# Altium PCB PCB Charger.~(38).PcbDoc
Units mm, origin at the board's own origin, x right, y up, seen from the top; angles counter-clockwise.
Board outline 70.24 x 66.94 mm, 2 copper layers (Top Layer, Bottom Layer), stack 1.57 mm thick; 117 components, 68 nets, 350 pads, 0 vias.
Unrouted connection lines stored in the file: 247.
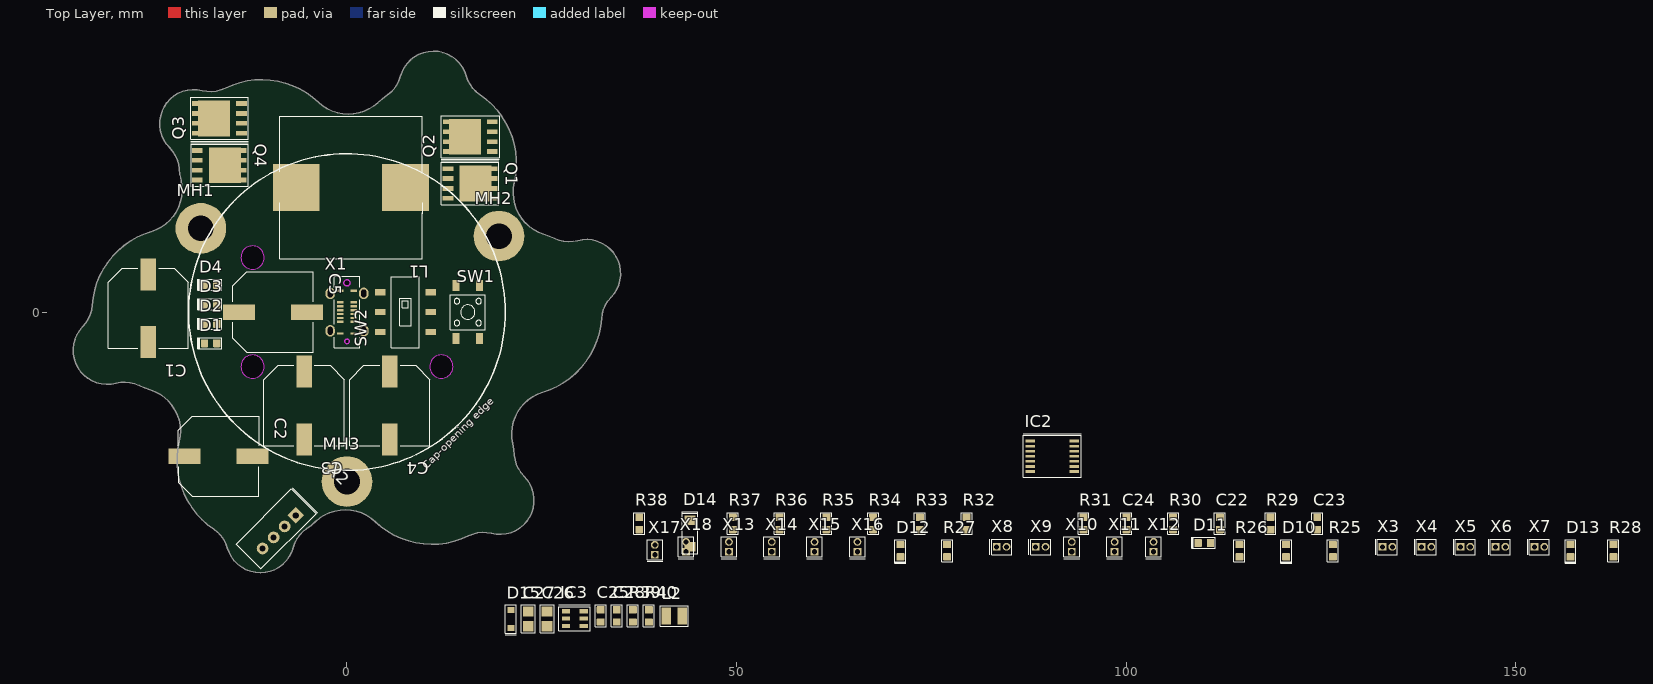
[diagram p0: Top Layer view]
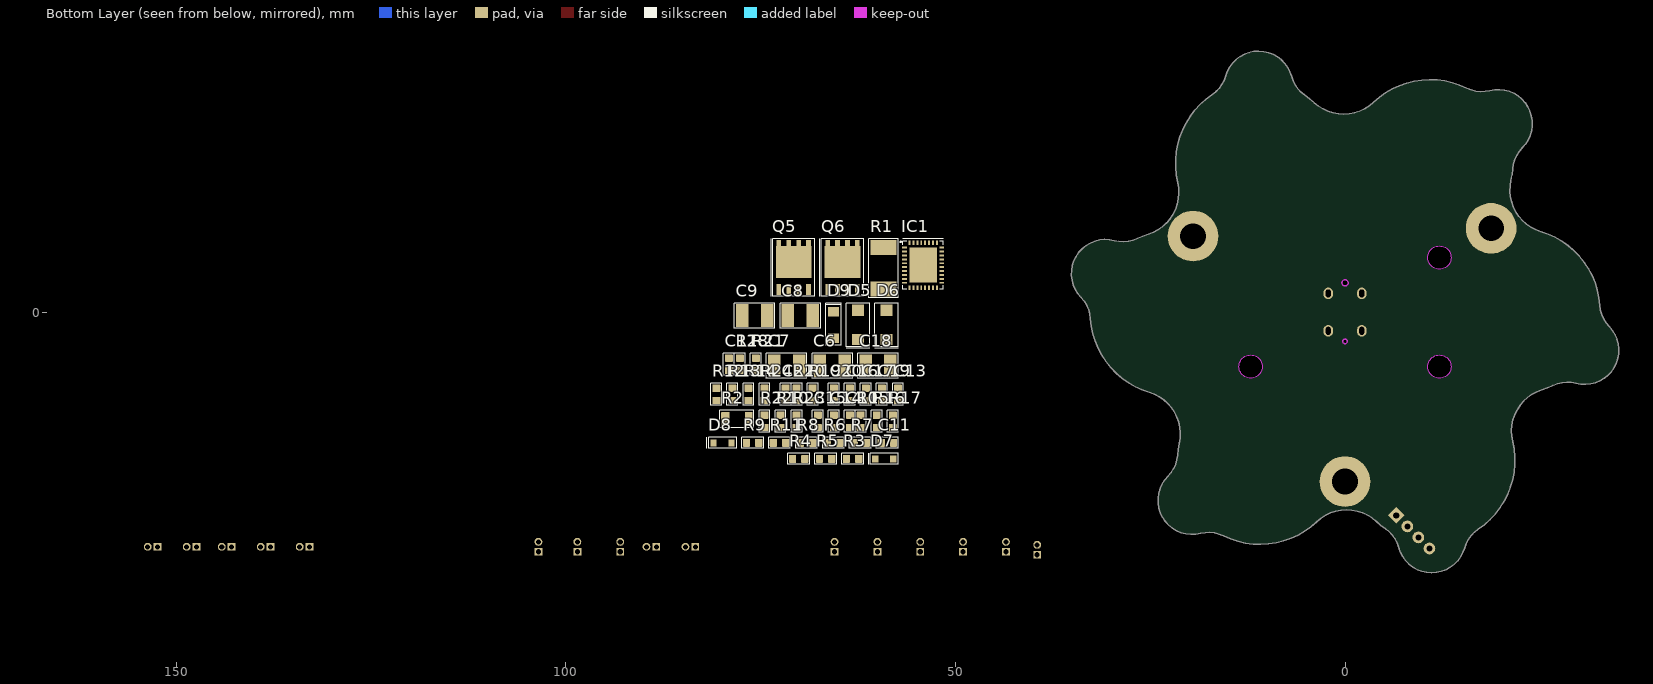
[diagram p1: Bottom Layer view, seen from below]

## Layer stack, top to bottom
Top Solder: solder mask 0.0102, Solder Resist, Dk 3.5
Top Layer: signal copper 0.0356
Dielectric 1: core 1.4986, Core-043, Dk 4.3
Bottom Layer: signal copper 0.0356
Bottom Solder: solder mask 0.0102, Solder Resist, Dk 3.5

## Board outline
331 vertices, not listed, extent -35.137,-33.454 35.107,33.486
cut-out: 10.61,-6.994 ccw(c12.11,-6.994) 12.11,-8.494 ccw(c12.11,-6.994) 13.61,-6.994 ccw(c12.11,-6.994) 12.11,-5.494 ccw(c12.11,-6.994)
cut-out: -13.61,6.994 ccw(c-12.11,6.994) -12.11,5.494 ccw(c-12.11,6.994) -10.61,6.994 ccw(c-12.11,6.994) -12.11,8.494 ccw(c-12.11,6.994)
cut-out: -13.609,-6.996 ccw(c-12.109,-6.996) -12.109,-8.496 ccw(c-12.109,-6.996) -10.609,-6.996 ccw(c-12.109,-6.996) -12.109,-5.496 ccw(c-12.109,-6.996)

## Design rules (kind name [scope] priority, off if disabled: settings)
Clearance [All] p1: gap=0.254 ignorepadtopadclearanceinfootprint=FALSE
PolygonConnect [All] p1: connectstyle=Relief reliefconductorwidth=0.254 reliefentries=4 polygonreliefangle="90 Angle" airgapwidth=0.254
RoutingVias [All] p1: holewidth=0.711 width=1.27 viastyle="Through Hole" minholewidth=0.711 minwidth=1.27 maxholewidth=0.711 maxwidth=1.27
SolderMaskExpansion [All] p1: expansion=0.102 istentingtop=FALSE
SupplyNets "Schematic Supply Nets_4" [InNet('5V_SoC')] p1: voltage=0.000
SupplyNets "Schematic Supply Nets_3" [InNet('12V')] p2: voltage=0.000
SupplyNets "Schematic Supply Nets_2" [InNet('5V')] p3: voltage=0.000
SupplyNets "Schematic Supply Nets_1" [InNet('3V3')] p4: voltage=0.000
SupplyNets "Schematic Supply Nets" [InNet('GND')] p5: voltage=0.000
Width [All] p1: maxlimit=0.254 minlimit=0.254 preferedwidth=0.254
30 further rules are at their usual default settings.

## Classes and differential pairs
component class "POWER DISTRIBUTION": C25 C26 C27 C28 D15 IC3 L2 R39 R40
component class "BATTERY LEVEL INDICATOR": C22 C23 C24 D14 IC2 R29 R30 R31 R32 R33 R34 R35 R36 R37 R38
component class CHARGER: C1 C2 C3 C4 C5 C6 C7 C8 C9 C10 C11 C12 C13 C14 C15 C16 C17 C18 C19 C20 C21 D5 D6 D7 D8 D9 D10 D11 D12 D13 IC1 L1 Q1 Q2 Q3 Q4 R1 R2 R3 R4 R5 R6 R7 R8 R9 R10 R11 R12 R13 R14 R15 R16 R17 R18 R19 R20 R21 R22 R23 R24 R25 R26 R27 R28 X3 X4 X5 X6 X7 X8 X9 X10 X11 X12 X13 X14 X15 X16 X17 X18
component class Arhitecture: D1 D2 D3 D4 MH1 MH2 MH3 Q5 Q6 SW1 SW2 X1 X2

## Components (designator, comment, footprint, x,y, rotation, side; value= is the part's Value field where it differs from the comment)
C1 "EEHZA1J560P" CAP_SMD_10X10.2 -25.5,0.5 r270 top
C2 "EEHZA1J560P" CAP_SMD_10X10.2 -16.5,-18.5 r0 top
C3 "EEHZA1J560P" CAP_SMD_10X10.2 -5.5,-12 r270 top
C4 "EEHZA1J560P" CAP_SMD_10X10.2 5.5,-12 r270 top
C5 "EEHZA1J560P" CAP_SMD_10X10.2 -9.5,0 r0 top
C6 "HMK325C7475KN-TE" CAP_1210 65.787,-6.899 r180 bottom
C7 "HMK325C7475KN-TE" CAP_1210 71.645,-6.899 r180 bottom
C8 "HMK325C7475KN-TE" CAP_1210 69.903,-0.441 r180 bottom
C9 "HMK325C7475KN-TE" CAP_1210 75.761,-0.441 r180 bottom
C10 "CL10A106MA8NRNC" "CAP 0603" 63.538,-14.015 r90 bottom
C11 "CL10A106MA8NRNC" "CAP 0603" 58.729,-16.773 r180 bottom
C12 "CC0603KRX7R0BB104" "CAP 0603" 79.054,-6.699 r90 bottom
C13 "CC0603KRX7R0BB104" "CAP 0603" 57.364,-10.557 r90 bottom
C14 "CC0603KRX7R0BB104" "CAP 0603" 65.596,-14.015 r90 bottom
C15 "CC0603KRX7R0BB104" "CAP 0603" 67.654,-14.015 r90 bottom
C16 "CL10B474KA8NNNC" "CAP 0603" 63.538,-10.557 r90 bottom
C17 "CL10B474KA8NNNC" "CAP 0603" 61.48,-10.557 r90 bottom
C18 "HMK325C7475KN-TE" CAP_1210 59.929,-6.899 r180 bottom
C19 "CL10A106MA8NRNC" "CAP 0603" 59.422,-10.557 r90 bottom
C20 "CL10A106MA8NRNC" "CAP 0603" 65.596,-10.557 r90 bottom
C21 "CC0603KRX7R9BB153" "CAP 0603" 71.77,-10.557 r90 bottom
C22 "CGA0603X5R226M100JT" "CAP 0603" 112.006,-27.118 r90 top
C23 "CGA0603X5R226M100JT" "CAP 0603" 124.506,-27.118 r90 top
C24 "CGA0603X5R226M100JT" "CAP 0603" 100.006,-27.118 r90 top
C25 "CL10A105KB8NNNC" "CAP 0603" 32.561,-38.983 r90 top
C26 "CL21A475KBQNNNE" Cap_0805 25.67,-39.358 r90 top
C27 "CL21A475KBQNNNE" Cap_0805 23.262,-39.358 r90 top
C28 "CL10A106MA8NRNC" "CAP 0603" 34.619,-38.983 r90 top
D1 "XL-1608SURC-06" DIODE_0603 -17.5,-4 r0 top
D2 "XL-1608SURC-06" DIODE_0603 -17.5,-1.5 r0 top
D3 "XL-1608SURC-06" DIODE_0603 -17.5,1 r0 top
D4 "XL-1608SURC-06" DIODE_0603 -17.5,3.5 r0 top
D5 "SS210F" SMAF 62.487,-1.641 r90 bottom
D6 "SS210F" SMAF 58.829,-1.641 r90 bottom
D7 "1N5819WS" SOD-323 59.129,-18.831 r180 bottom
D8 "1N5819WS" SOD-323 79.877,-16.773 r180 bottom
D9 "BZT52C3V0" SOD-123 65.645,-3.341 r90 bottom
D10 "XL-1608UOC-06" DIODE_0603 120.506,-30.618 r90 top
D11 "XL-1608UOC-06" DIODE_0603 110.006,-29.618 r0 top
D12 "PSC-1608U52GC-G4" DIODE_0603 71.006,-30.618 r90 top
D13 "XL-1608UOC-06" DIODE_0603 157.006,-30.618 r90 top
D14 "BZT52C3V0" SOD-123 44.006,-30.118 r90 top
D15 "1N5819WS" SOD-323 21.029,-39.383 r90 top
IC1 "BQ25756RRVR" VQFN-36(5x6) 54.131,6.017 r180 bottom
IC2 "LM339LVPWR" TSSOP-14 90.5,-18.5 r0 top
IC3 "LV2842XLVDDCR" SOT-23-6 28.103,-38.383 r0 top
L1 "MTF1810-150M" MTF1810-150M 0.5,16 r180 top
L2 "FTC252012S100MBCA" "IND 1008" 42,-39 r0 top
MH1 "M?" "M3 Plated" -18.75,10.75 r0 top locked
MH2 "M?" "M3 Plated" 19.5,9.75 r0 top locked
MH3 "M?" "M3 Plated" 0,-21.75 r0 top locked
Q1 "CRSM038N10N4" "DFN-8 (5x6)" 16.5,16.5 r270 top
Q2 "CRSM038N10N4" "DFN-8 (5x6)" 15.118,22.506 r90 top
Q3 "CRSM038N10N4" "DFN-8 (5x6)" -17.061,24.854 r90 top
Q4 "CRSM038N10N4" "DFN-8 (5x6)" -15.678,18.847 r270 top
Q5 "E060N2P3HL1" "DFN-8 (5x6)" 70.745,6.417 r180 bottom
Q6 "E060N2P3HL1" "DFN-8 (5x6)" 64.487,6.417 r180 bottom
R1 "Pd = 1W" RES_2512 59.229,5.617 r90 bottom
R2 "Pd = 0.125 W" RES_1206 78.051,-13.715 r180 bottom
R3 "0603WAF100JT5E" RES_0603 63.187,-18.831 r180 bottom
R4 "0603WAF100JT5E" RES_0603 70.103,-18.831 r180 bottom
R5 "0603WAF100JT5E" RES_0603 66.645,-18.831 r180 bottom
R6 "0603WAF100JT5E" RES_0603 65.645,-16.773 r180 bottom
R7 "0603WAF1004T5E" RES_0603 62.187,-16.773 r180 bottom
R8 "0603WAF3483T5E" RES_0603 69.103,-16.773 r180 bottom
R9 "0603WAF3012T5E" RES_0603 76.019,-16.773 r180 bottom
R10 "0603WAF220KT5E" RES_0603 72.435,-14.015 r90 bottom
R11 "0603WAF220KT5E" RES_0603 72.561,-16.773 r180 bottom
R12 "0603WAF220KT5E" RES_0603 80.667,-10.557 r90 bottom
R13 "0603WAF220KT5E" RES_0603 78.609,-10.557 r90 bottom
R14 "0603WAF220KT5E" RES_0603 76.551,-10.557 r90 bottom
R15 "0603WAF220KT5E" RES_0603 62.145,-14.015 r90 bottom
R16 "RT0603BRD07249KL" RES_0603 60.087,-14.015 r90 bottom
R17 "RT0603BRD0713K8L" RES_0603 58.029,-14.015 r90 bottom
R18 "I_IN_LIM = 5.5 A" RES_0603 77.661,-6.699 r90 bottom
R19 "F_sw = 200 kHz" RES_0603 68.319,-10.557 r90 bottom
R20 "I_CHG_MAX = 15 A" RES_0603 70.377,-10.557 r90 bottom
R21 "0603WAF0000T5E" RES_0603 75.603,-6.699 r90 bottom
R22 "0603WAF0000T5E" RES_0603 74.493,-14.015 r90 bottom
R23 "0603WAF5761T5E" RES_0603 70.377,-14.015 r90 bottom
R24 "Place NTC next to hottest fet." RES_0603 74.493,-10.557 r90 bottom
R25 "0603WAF4532T5E" RES_0603 126.506,-30.618 r90 top
R26 "0603WAF1002T5E" RES_0603 114.506,-30.618 r90 top
R27 "0603WAF1002T5E" RES_0603 77.006,-30.618 r90 top
R28 "0603WAF4532T5E" RES_0603 162.506,-30.618 r90 top
R29 "0603WAF2001T5E" RES_0603 118.506,-27.118 r90 top
R30 "0603WAF8662T5E" RES_0603 106.006,-27.118 r90 top
R31 "0603WAF5101T5E" RES_0603 94.506,-27.118 r90 top
R32 "FRC0603F7870TS" RES_0603 79.506,-27.118 r90 top
R33 "0603WAF5101T5E" RES_0603 73.506,-27.118 r90 top
R34 "RC0603FR-07698RL" RES_0603 67.506,-27.118 r90 top
R35 "0603WAF5101T5E" RES_0603 61.506,-27.118 r90 top
R36 "RT0603BRD07626RL" RES_0603 55.506,-27.118 r90 top
R37 "0603WAF5101T5E" RES_0603 49.506,-27.118 r90 top
R38 "FRC0603F1132TS" RES_0603 37.506,-27.118 r90 top
R39 "0603WAF1473T5E" RES_0603 36.677,-38.983 r90 top
R40 "0603WAF1002T5E" RES_0603 38.735,-38.983 r90 top
SW1 "TS4560TP" TS4560TP 15.5,0 r90 top
SW2 "SS-3235S-L3" SS-3235S-L3 7.5,0 r90 top
X1 "TYPE-C 16P LTH6.8" "TYPE-C 16P LTH6.8" 0,0 r90 top
X2 "B4B-PH-K-S(LF)(SN)" B4B-PH-K-S(LF)(SN) -8.707,-28.207 r45 top
X3 "ZX-PZ1.27-1-2PZZ" "Pin header 1x2 1.27mmP THT Vertical" 133.506,-30.118 r0 top
X4 "ZX-PZ1.27-1-2PZZ" "Pin header 1x2 1.27mmP THT Vertical" 138.506,-30.118 r0 top
X5 "ZX-PZ1.27-1-2PZZ" "Pin header 1x2 1.27mmP THT Vertical" 143.506,-30.118 r0 top
X6 "ZX-PZ1.27-1-2PZZ" "Pin header 1x2 1.27mmP THT Vertical" 148.006,-30.118 r0 top
X7 "ZX-PZ1.27-1-2PZZ" "Pin header 1x2 1.27mmP THT Vertical" 153.006,-30.118 r0 top
X8 "ZX-PZ1.27-1-2PZZ" "Pin header 1x2 1.27mmP THT Vertical" 84.006,-30.118 r0 top
X9 "ZX-PZ1.27-1-2PZZ" "Pin header 1x2 1.27mmP THT Vertical" 89.006,-30.118 r0 top
X10 "ZX-PZ1.27-1-2PZZ" "Pin header 1x2 1.27mmP THT Vertical" 93.006,-30.118 r90 top
X11 "ZX-PZ1.27-1-2PZZ" "Pin header 1x2 1.27mmP THT Vertical" 98.506,-30.118 r90 top
X12 "ZX-PZ1.27-1-2PZZ" "Pin header 1x2 1.27mmP THT Vertical" 103.506,-30.118 r90 top
X13 "ZX-PZ1.27-1-2PZZ" "Pin header 1x2 1.27mmP THT Vertical" 49.006,-30.118 r90 top
X14 "ZX-PZ1.27-1-2PZZ" "Pin header 1x2 1.27mmP THT Vertical" 54.506,-30.118 r90 top
X15 "ZX-PZ1.27-1-2PZZ" "Pin header 1x2 1.27mmP THT Vertical" 60.006,-30.118 r90 top
X16 "ZX-PZ1.27-1-2PZZ" "Pin header 1x2 1.27mmP THT Vertical" 65.506,-30.118 r90 top
X17 "ZX-PZ1.27-1-2PZZ" "Pin header 1x2 1.27mmP THT Vertical" 39.5,-30.5 r90 top
X18 "ZX-PZ1.27-1-2PZZ" "Pin header 1x2 1.27mmP THT Vertical" 43.506,-30.118 r90 top

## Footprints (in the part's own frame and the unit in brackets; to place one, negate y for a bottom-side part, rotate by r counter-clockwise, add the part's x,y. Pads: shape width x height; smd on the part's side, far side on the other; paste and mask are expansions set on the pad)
B4B-PH-K-S(LF)(SN) [mm] "JST PH 2.00mm 1x4 THT Vertical"
  rect 1.5x1.5 hole 0.8: 1(3,0)
  round 1.5 hole 0.8: 2(1,0) 3(-1,0) 4(-3,0)
  silkscreen extent -5,-1.7 5.2,2.8, body extent -4.95,-1.7 4.95,2.8, height 6.01
"CAP 0603" [mm] "CAP 0603"
  rrect20% 0.94x1.02 smd: 1(-0.79,0) 2(0.79,0)
  silkscreen extent -1.4,-0.7 1.4,0.7, body extent -0.8,-0.5 0.8,0.47, height 0.81
Cap_0805 [mm]
  rect 1.312x1.396 smd paste+0 mask+0: 1(-0.948,0) 2(0.948,0)
  silkscreen extent -1.8,-0.9 1.8,0.9, body extent -1.05,-0.67 1.05,0.67, height 1.35
CAP_1210 [mm] "Cap SMD 1210"
  rect 1.6x2.904 smd: 1(-1.6,0) 2(1.6,0)
  silkscreen extent -2.6,-1.6 2.6,1.6, body extent -1.6,-1.35 1.6,1.35, height 2.51
CAP_SMD_10X10.2 [mm] "Elko, radial SMD FI10xH10.2mm"
  rect 4.1x2 smd: +(-4.35,0) -(4.35,0)
  silkscreen extent -5.15,-5.15 5.15,5.15, body extent -5.85,-5.15 5.85,5.15, height 10.21
"DFN-8 (5x6)" [mil] "Mosfet SMD footprint"
  rect 24x55 smd paste-3937.01 mask+2: D(-75,83) D(-25,83) D(25,83) D(75,83) G(75,-139) S(-75,-139) S(-25,-139) S(25,-139)
  rect 181.1x161.42 smd paste-3937.01 mask+2: D(0,0)
  silkscreen extent -114,-173 106,118, body extent -101,-150 101,93, height 42
DIODE_0603 [mm] "RES 0603"
  rrect20% 0.94x1.02 smd: A(0.79,0) K(-0.79,0)
  silkscreen extent -1.63,-0.7 1.4,0.7, body extent -0.8,-0.4 0.8,0.4, height 0.46
"IND 1008" [mm] "Power inductor SMD 1008"
  rect 1.2x2.2 smd: 1(-1.028,0) 2(1.028,0)
  silkscreen extent -1.8,-1.3 1.8,1.3, body extent -1.26,-1 1.26,1, height 1.21
"M3 Plated" [mm] "M3 hole"
  round 6.5 hole 3.3: 1(0,0)
MTF1810-150M [mm] "Inductor SMD 18.2x18.2x8.9 mm"
  rect 6x6 smd: 1(-7,0) 2(7,0)
  silkscreen extent -9.14,-9.14 9.14,9.14, body extent -9.2,-9.11 9.1,9.11, height 9.02
"Pin header 1x2 1.27mmP THT Vertical" [mm] "Pin header 1x2 1.27mmP THT Vertical"
  rect 1x1 hole 0.65: 1(-0.635,0)
  round 1 hole 0.65: 2(0.635,0)
  silkscreen extent -1.5,-1 1.28,1, body extent -1.28,-1 1.28,1, height 4.91
RES_0603 [mm] "RES 0603"
  rrect20% 0.94x1.02 smd: 1(-0.79,0) 2(0.79,0)
  silkscreen extent -1.4,-0.7 1.4,0.7, body extent -0.8,-0.4 0.8,0.4, height 0.46
RES_1206 [mm]
  rrect14% 1.09x1.77 smd: 1(-1.465,0)
  rrect14% 0.94x1.77 smd: 2(1.54,0)
  silkscreen extent -2.2,-1.1 2.2,1.1, body extent -1.55,-0.77 1.55,0.78, height 0.56
RES_2512 [mm] "Generic resistor footprint"
  rrect7% 1.9x3.37 smd: 1(-2.66,0) 2(2.66,0)
  silkscreen extent -3.8,-1.9 3.8,1.9, body extent -3.18,-1.57 3.17,1.58, height 0.75
SMAF [mm] "DIODE SMAF"
  rect 1.46x1.53 smd: A(1.875,0) K(-1.875,0)
  silkscreen extent -3,-1.5 2.8,1.5, body extent -2.3,-1.3 2.3,1.3, height 1.11
SOD-123 [mm] "Diode FP"
  rect 1.2x1.4 smd: A(0,0) K(3.4,0)
  silkscreen extent -0.9,-1 4.5,1, body extent -0.13,-0.77 3.52,0.77, height 1.44
SOD-323 [mm] "Diode package"
  rect 0.8x0.9 smd: A(1.15,0) K(-1.15,0)
  silkscreen extent -2,-0.7 1.8,0.7, body extent -1.25,-0.63 1.25,0.63, height 1.11
SOT-23-6 [mm]
  rect 1.072x0.532 smd: 1(0,0) 2(0,-0.95) 3(0,-1.9) 4(2.298,-1.9) 5(2.298,-0.95) 6(2.298,0)
  silkscreen extent -0.9,-2.5 3.1,0.8, body extent -0.3,-2.35 2.5,0.55, height 1.2
SS-3235S-L3 [mm] "Slide switch"
  rect 0.8x1.35 smd: 1(-2.54,3.25) 1(-2.54,-3.25) 2(0,3.25) 2(0,-3.25) 3(2.54,3.25) 3(2.54,-3.25)
  silkscreen extent -4.55,-1.8 4.55,1.8, body extent -4.6,-3.45 4.5,3.45, height 7.56
TS4560TP [mm] "Switch tactile 4.5x4.5mm 6mmH"
  rect 1.4x0.9 smd: 1(-3.4,1.5) 2(3.4,1.5) 3(-3.4,-1.5) 4(3.4,-1.5)
  silkscreen extent -2.25,-2.25 2.25,2.25, body extent -3.25,-2.25 3.25,2.25, height 7.51
TSSOP-14 [mm] "TSSOP-14"
  rect 1.2x0.35 smd: 1(-2.825,1.95) 2(-2.825,1.3) 3(-2.825,0.65) 4(-2.825,0) 5(-2.825,-0.65) 6(-2.825,-1.3) 7(-2.825,-1.95) 8(2.825,-1.95) 9(2.825,-1.3) 10(2.825,-0.65) 11(2.825,0) 12(2.825,0.65) 13(2.825,1.3) 14(2.825,1.95)
  silkscreen extent -3.7,-2.7 3.7,2.9, body extent -3.2,-2.5 3.2,2.5, height 1.2
"TYPE-C 16P LTH6.8" [mm] "USB C 16P SMD Vertical 6.8mmH"
  rect 0.3x0.87 smd mask+0.051: A1(-2.75,0.865) A4(-1.25,0.865) A5(-0.75,0.865) A6(-0.25,0.865) A7(0.25,0.865) A8(0.75,0.865) A9(1.25,0.865) A12(2.75,0.865) B1(2.75,-0.865) B4(1.25,-0.865) B5(0.75,-0.865) B6(0.25,-0.865) B7(-0.25,-0.865) B8(-0.75,-0.865) B9(-1.25,-0.865) B12(-2.75,-0.865)
  oval 1.5x1.2 hole 0.61 slot 1 at 0 deg: CASE(-2.4,-2.15) CASE(-2.4,2.15) CASE(2.4,-2.15)
  oval 1.5x1.2 hole 0.61 slot 1 at 0 deg copper offset 0,0: CASE(2.4,2.15)
  Keep-Out Layer board cut-out: -3.45,0 -3.48,-0.13 -3.563,-0.234 -3.683,-0.292 -3.817,-0.292 -3.937,-0.234 -4.02,-0.13 -4.05,0 -4.05,0 -4.02,0.13 -3.937,0.235 -3.817,0.293 -3.683,0.293 -3.563,0.235 -3.48,0.13 -3.45,0
  Keep-Out Layer board cut-out: 4.15,0 4.111,-0.174 4,-0.313 3.839,-0.39 3.661,-0.39 3.501,-0.313 3.39,-0.174 3.35,0 3.35,0 3.39,0.174 3.501,0.313 3.661,0.39 3.839,0.39 4,0.313 4.111,0.174 4.15,0
  Keep-Out Layer circle w0.025: c-3.75,0 r0.3
  Keep-Out Layer circle w0.025: c3.75,0 r0.4
  Keep-Out Layer region: -3.45,0 -3.48,-0.13 -3.563,-0.234 -3.683,-0.292 -3.817,-0.292 -3.937,-0.234 -4.02,-0.13 -4.05,0 -4.05,0 -4.02,0.13 -3.937,0.235 -3.817,0.293 -3.683,0.293 -3.563,0.235 -3.48,0.13 -3.45,0
  Keep-Out Layer region: 4.15,0 4.111,-0.174 4,-0.313 3.839,-0.39 3.661,-0.39 3.501,-0.313 3.39,-0.174 3.35,0 3.35,0 3.39,0.174 3.501,0.313 3.661,0.39 3.839,0.39 4,0.313 4.111,0.174 4.15,0
  silkscreen extent -4.57,-1.65 4.57,1.65, body extent -4.47,-2.3 4.47,2.3, height 6.51
VQFN-36(5x6) [mm] "TI IC"
  rect 0.6x0.25 smd mask+0.07: 1(-2.4,2.25)
  rect 0.6x0.25 smd paste+0 mask+0.07: 2(-2.4,1.75) 3(-2.4,1.25) 4(-2.4,0.75) 5(-2.4,0.25) 6(-2.4,-0.25) 7(-2.4,-0.75) 8(-2.4,-1.25) 9(-2.4,-1.75) 10(-2.4,-2.25) 19(2.4,-2.25) 20(2.4,-1.75) 21(2.4,-1.25) 22(2.4,-0.75) 23(2.4,-0.25) 24(2.4,0.25) 25(2.4,0.75) 26(2.4,1.25) 27(2.4,1.75) 28(2.4,2.25)
  rect 0.25x0.6 smd paste+0 mask+0.07: 11(-1.75,-2.9) 12(-1.25,-2.9) 13(-0.75,-2.9) 14(-0.25,-2.9) 15(0.25,-2.9) 16(0.75,-2.9) 17(1.25,-2.9) 18(1.75,-2.9) 29(1.75,2.9) 30(1.25,2.9) 31(0.75,2.9) 32(0.25,2.9) 33(-0.25,2.9) 34(-0.75,2.9) 35(-1.25,2.9) 36(-1.75,2.9)
  rect 3.5x4.5 smd paste-100 mask+0.051: 37(0,0)
  silkscreen extent -2.91,-3.1 2.6,3.4, body extent -2.51,-3 2.51,3.02, height 0.76

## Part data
C1 C2 C3 C4 C5: "Cap AL-EL 56uF 63V 30mR 1.8Ar SMD 10x10.2mm", Capacitance=56u, Manufacturer=Panasonic, Supplier Part Number 1=?, Voltage Rating=63V
C6 C7 C8 C9 C18: "Cap 4.7uF 100V 1210 X7R", Capacitance=4u7, Case Code (Imperial)=1210, Manufacturer="Taiyo Yuden", Supplier Part Number 1=?, Voltage Rating=100V
C10 C11 C19 C20 C28: "Cap 10uF 25V 0603 X5R", Capacitance=10u, Case Code (Imperial)=0603, Manufacturer=Samsung, Supplier Part Number 1=?, Voltage Rating=25V
C12 C13 C14 C15: "Cap 100nF 100V 0603 X7R", Capacitance=100n, Case Code (Imperial)=0603, Manufacturer=YAGEO, Supplier Part Number 1=?, Voltage Rating=100V
C16 C17: "Cap 470nF 25V 0603 X7R", Capacitance=470n, Case Code (Imperial)=0603, Manufacturer=Samsung, Supplier Part Number 1=?, Voltage Rating=25V
C21: "Cap 15nF 50V 0603 X7R", Capacitance=15n, Case Code (Imperial)=0603, Manufacturer=Yageo, Manufacturer Part Number=CC0603KRX7R9BB104, Supplier Part Number 1=?, Voltage Rating=50V
C22 C23 C24: "Cap 22uF 10V 0603 X5R", Capacitance=22u, Case Code (Imperial)=0603, Manufacturer=HRE, Supplier Part Number 1=?, Voltage Rating=10V
C25: "Cap 1uF 50V 0603 X5R", Capacitance=1u, Case Code (Imperial)=0603, Manufacturer=Samsung, Supplier Part Number 1=?, Voltage Rating=50V
C26 C27: "Cap 4.7uF 50V 0805 X5R", Capacitance=4u7, Case Code (Imperial)=0805, Manufacturer=Samsung, Supplier Part Number 1=?, Voltage Rating=50V
D1 D2 D3 D4: "LED Red 0603 25mA", Manufacturer=Xinglight
D5 D6: "Schottky 100V 2A 850mVf SMAF", Forward Current=2A, Manufacturer=GOODWORK, Reverse Voltage=100V, Supplier Part Number 1=?
D7 D8 D15: "Schottky 40V 1A 600mVf SOD-323", Forward Current=1A, Manufacturer="Guangdong Hottech", Reverse Voltage=40V, Supplier Part Number 1=?
D9 D14: "Zener 3.0V 500mW SOD-123", Manufacturer="Shandong Jingdao Microelectronics", Power Rating=500mW, Reverse Voltage=3V, Supplier Part Number 1=?
D10 D11 D13: "LED Orange 0603 20mA", Manufacturer=XINGLIGHT
D12: "LED Green 0603 20mA", Manufacturer=HONGLITRONIC
IC1: "Charger IC", Manufacturer="Texas Instruments"
IC2: "Comparator Quad 1.65~5.5V TSSOP-14", Manufacturer="Texas Instruments"
IC3: "Step-down converter 4~40Vin 600mAout Adjustible SOT23-6", Manufacturer="Texas Instruments"
L1: "Inductor 15uH 22Asat 10mR SMD 18x18x9 mm", Inductance=15uH, Manufacturer=COILMX, Resistance=10mR, Saturation current=22Asat, Supplier Part Number 1=?
L2: "Inductor 10uH 1.6Asat 330mR", Inductance=10uH, Manufacturer=cjiang, Resistance=330mR, Saturation current=1.6Asat, Supplier Part Number 1=?
MH1 MH2 MH3: library part "Mounting hole", "Generic mounting hole symbol"
Q1 Q2 Q3 Q4: "Nmos 100V 100A 3.6mR DFN-8(5x6)", Manufacturer=CRMICRO, Voltage=100V
Q5 Q6: "Nmos 60V 180A 2.3mR PDFN5x6-8", Manufacturer=Existar, Voltage=60V
R1: library part RLM25FEER005, "Res 5mR 2512 1% 2W", Case Code (Imperial)=2512, Manufacturer="TA-I Tech", Power Rating=2W, Resistance=5mR, Resistance Tolerance=1%, Supplier Part Number 1=?
R2: library part FRM121WFR005TM, "Res 5mR 1206 1% 1W", Case Code (Imperial)=1206, Manufacturer=FOJAN, Power Rating=1W, Resistance=5mR, Resistance Tolerance=1%, Supplier Part Number 1=?
R3 R4 R5 R6: "Res 10R 0603 1% 100mW 75V", Case Code (Imperial)=0603, Manufacturer=Uni-Royal, Power Rating=100mW, Resistance=10R, Resistance Tolerance=1%, Supplier Part Number 1=?
R7: "Res 1M 0603 1% 100mW 75V", Case Code (Imperial)=0603, Manufacturer=Uni-Royal, Power Rating=100mW, Resistance=1M, Resistance Tolerance=1%, Supplier Part Number 1=?
R8: "Res 348k 0603 1% 100mW 75V", Case Code (Imperial)=0603, Manufacturer=Uni-Royal, Power Rating=100mW, Resistance=348k, Resistance Tolerance=1%, Supplier Part Number 1=?
R9: "Res 30k1 0603 1% 100mW 75V", Case Code (Imperial)=0603, Manufacturer=Uni-Royal, Power Rating=100mW, Resistance=30k1, Resistance Tolerance=1%, Supplier Part Number 1=?
R10 R11 R12 R13 R14 R15: "Res 2R2 0603 1% 100mW 75V", Case Code (Imperial)=0603, Manufacturer=Uni-Royal, Power Rating=100mW, Resistance=2R2, Resistance Tolerance=1%, Supplier Part Number 1=?
R16: "Res 249K 0603 0.1% 100mW 75V", Case Code (Imperial)=0603, Manufacturer=YAGEO, Power Rating=100mW, Resistance=249K, Resistance Tolerance=0%1, Supplier Part Number 1=?
R17: "Res 13.8k 0603 0.1% 100mW 75V", Case Code (Imperial)=0603, Manufacturer=YAGEO, Power Rating=100mW, Resistance=13k8, Resistance Tolerance=0%1, Supplier Part Number 1=?
R18: library part FRC0603F3741TS, "Res 3K74 0603 1% 100mW 75V", Case Code (Imperial)=0603, Manufacturer=FOJAN, Power Rating=100mW, Resistance=3k74, Resistance Tolerance=1%, Supplier Part Number 1=?
R19: library part 0603WAF2003T5E, "Res 200K 0603 1% 100mW 75V", Case Code (Imperial)=0603, Manufacturer=UNI-ROYAL, Power Rating=100mW, Resistance=200k, Resistance Tolerance=1%, Supplier Part Number 1=?
R20: library part 0603WAF3321T5E, "Res 3k32 0603 1% 100mW 75V", Case Code (Imperial)=0603, Manufacturer=UNI-ROYAL, Power Rating=100mW, Resistance=3k32, Resistance Tolerance=1%, Supplier Part Number 1=?
R21 R22: "Res 0R 0603 1% 100mW 75V", Case Code (Imperial)=0603, Manufacturer=UNI-ROYAL, Power Rating=100mW, Resistance=0R, Resistance Tolerance=1%, Supplier Part Number 1=?
R23: "Res 5k76 0603 1% 100mW 75V", Case Code (Imperial)=0603, Manufacturer=Uni-Royal, Power Rating=100mW, Resistance=5k76, Resistance Tolerance=1%, Supplier Part Number 1=?
R24: library part NCP18XH103F03RB, "NTC 10k 0603 1% 3455K", Case Code (Imperial)=0603, Manufacturer=Murata, Resistance=10k, Supplier Part Number 1=?
R25 R28: "Res 45k3 0603 1% 100mW 75V", Case Code (Imperial)=0603, Manufacturer=Uni-Royal, Power Rating=100mW, Resistance=45k3, Resistance Tolerance=1%, Supplier Part Number 1=?
R26 R27 R40: "Res 10k 0603 1% 100mW 75V", Case Code (Imperial)=0603, Manufacturer=Uni-Royal, Power Rating=100mW, Resistance=10k, Resistance Tolerance=1%, Supplier Part Number 1=?
R29: "Res 2k 0603 1% 100mW 75V", Case Code (Imperial)=0603, Manufacturer=Uni-Royal, Power Rating=100mW, Resistance=2k, Resistance Tolerance=1%, Supplier Part Number 1=?
R30: "Res 86k6 0603 1% 100mW 75V", Case Code (Imperial)=0603, Manufacturer=Uni-Royal, Power Rating=100mW, Resistance=86k6, Resistance Tolerance=1%, Supplier Part Number 1=?
R31 R33 R35 R37: "Res 5k1 0603 1% 100mW 75V", Case Code (Imperial)=0603, Manufacturer=Uni-Royal, Power Rating=100mW, Resistance=5k1, Resistance Tolerance=1%, Supplier Part Number 1=?
R32: "Res 787R 0603 1% 100mW 75V", Case Code (Imperial)=0603, Manufacturer=FOJAN, Power Rating=100mW, Resistance=787R, Resistance Tolerance=1%, Supplier Part Number 1=?
R34: "Res 698R 0603 1% 100mW 75V", Case Code (Imperial)=0603, Manufacturer=YAGEO, Power Rating=100mW, Resistance=698R, Resistance Tolerance=1%, Supplier Part Number 1=?
R36: "Res 626R 0603 1% 100mW 75V", Case Code (Imperial)=0603, Manufacturer=YAGEO, Power Rating=100mW, Resistance=626R, Resistance Tolerance=1%, Supplier Part Number 1=?
R38: "Res 11k3 0603 1% 100mW 75V", Case Code (Imperial)=0603, Manufacturer=Fojan, Power Rating=100mW, Resistance=11k3, Resistance Tolerance=1%, Supplier Part Number 1=?
R39: "Res 147k 0603 1% 100mW 75V", Case Code (Imperial)=0603, Manufacturer=Uni-Royal, Power Rating=100mW, Resistance=147k, Resistance Tolerance=1%, Supplier Part Number 1=?
SW1: "Switch Tactile SMD 4.5x4.5mm 6mmH SPST", Manufacturer="Shou Han"
SW2: "Switch Slide SMD 9.1x3.5mm 6.6mmH", Manufacturer="XKB Connection"
X1: "USB-C 16P SMD Vertical 6.50mmH", Manufacturer="Shou Han"
X2: "Pin header 1x4 2.00mmP THT Vertical JST PH", Manufacturer=JST
X3 X4 X5 X6 X7 X8 X9 X10 X11 X12 X13 X14 X15 X16 X17 X18: "Pin header 1x2 1.27mmP THT Vertical", Manufacturer=Megastar

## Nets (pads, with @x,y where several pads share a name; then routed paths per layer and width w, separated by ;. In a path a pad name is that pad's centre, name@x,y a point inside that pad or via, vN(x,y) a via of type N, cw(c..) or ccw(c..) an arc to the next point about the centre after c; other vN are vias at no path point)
3V3: X2.1
5V: SW1.1 SW1.2
5V_SoC: C22.2 C23.1 IC2.3 R29.2 SW1.3 SW1.4
12V: C28.2 D8.A L2.2 R39.2
ACN: C13.2 C16.2 IC1.29 R4.1 X16.2
ACOV: IC1.35 R8.1 R9.2
ACP: C12.1 C16.1 IC1.30 R3.1 X16.1
ACUV: IC1.34 R7.1 R8.2
BTST1: C10.1 D5.K IC1.26
BTST2: C11.2 D6.K IC1.20
DRV_SUP: C19.2 D7.K D8.K IC1.23 R14.1 R15.2 X5.1
FB: IC1.12 R16.1 R17.2 X15.1
FB_12V: IC3.3 R39.1 R40.2
FBG: IC1.11 R17.1
FSW_SYNC: IC1.36 R19.2
G_H1: Q1.G R10.2 X3.1
G_H2: Q2.G R13.2 X4.1
G_L1: Q3.G R11.2 X13.1
G_L2: Q4.G R12.2 X14.1
GND: C1.- C2.- C3.- C4.- C5.- C6.1 C7.1 C8.1 C9.1 C12.2 C13.1 C14.2 C15.1 C18.1 C19.1 C20.1 C21.1 C22.1 C23.2 C24.1 C26.1 C27.1 C28.1 D1.K D2.K D3.K D4.K D9.A D14.A D15.A IC1.7 IC1.15 IC1.16 IC1.17 IC1.22 IC1.31 IC1.37 IC2.12 IC3.2 MH2.1 Q3.S Q4.S R9.1 R18.1 R19.1 R20.1 R24.1 R25.2 R26.2 R28.2 R38.1 R40.1 X1.A1 X1.A12 X1.B1 X1.B12 X1.CASE X2.2 X5.2 X6.2 X7.2 X8.2 X9.2 X10.2 X11.2 X12.2 X13.2 X14.2 X15.2 X17.2
HIDRV1: IC1.27 R10.1
HIDRV2: IC1.19 R13.1
ICHG: IC1.9 R20.2
ILIM_HIZ: IC1.10 R18.2
IN1+: IC2.5 R30.1 R32.2
IN1-: D14.K IC2.4 IC2.6 IC2.8 IC2.10 R29.1
IN2+: IC2.7 R32.1 R34.2
IN3+: IC2.9 R34.1 R36.2
IN4+: IC2.11 R36.1 R38.2
LODRV1: IC1.25 R11.1
LODRV2: IC1.21 R12.1
NetC25_1: C25.1 IC3.1
NetD1_A: D1.A R31.2
NetD2_A: D2.A R33.2
NetD3_A: D3.A R35.2
NetD4_A: D4.A R37.2
NetD5_A: D5.A R14.2
NetD6_A: D6.A R15.1
NetD10_K: D10.K R25.1
NetD11_K: D11.K R26.1
NetD12_A: D12.A R27.1
NetD13_K: D13.K R28.1
NetMH3_1: MH3.1 SW2.1
NetQ5_D: Q5.D X1.A4 X1.A9 X1.B4 X1.B9
NetQ5_G: Q5.G Q6.G
NetQ5_S: Q5.S Q6.S
NetX1_A5: X1.A5
NetX1_B5: X1.B5
nPG: D12.K IC1.6
OUT1: IC2.2 R31.1
OUT2: IC2.1 R33.1
OUT3: IC2.14 R35.1
OUT4: IC2.13 R37.1
PACK+: C24.2 C26.2 C27.2 D10.A IC3.4 IC3.5 MH1.1 R1.2 R6.2 R16.2 R30.2 SW2.2 X11.1
REGN: C20.2 D7.A D11.A IC1.24 R23.2 R27.2 X10.1
SCL: R21.1 X2.3 X7.1
SCL_BQ: IC1.1 R21.2
SDA: R22.1 X2.4 X12.1
SDA_BQ: IC1.2 R22.2
SRN: C15.2 C17.2 IC1.13 R6.1 X18.2
SRP: C14.1 C17.1 IC1.14 R5.1 X18.1
SW: C25.2 D15.K IC3.6 L2.1
SW1: C10.2 IC1.28 L1.1 Q1.S Q3.D X3.2 X8.1
SW2: C11.1 IC1.18 L1.2 Q2.S Q4.D X4.2 X9.1
TS: C21.2 D9.K IC1.8 R23.1 R24.2 X17.1
V_CHG_IN: C18.2 D13.A IC1.32 IC1.33 Q6.D R2.1 R3.2 R7.2 X6.1
V_HB_IN: C1.+ C6.2 C7.2 Q1.D R2.2 R4.2
V_HB_OUT: C2.+ C3.+ C4.+ C5.+ C8.2 C9.2 Q2.D R1.1 R5.2
pads on no net: IC1.3 IC1.4 IC1.5 SW2.3 X1.A6 X1.A7 X1.A8 X1.B6 X1.B7 X1.B8

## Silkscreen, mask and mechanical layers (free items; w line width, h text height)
Top Overlay:
  circle w0.2: c0,0 r20.32
  text "Cap-opening edge" at 10.257,-20.214 h1 r45
Board:
  drawing of 334 lines, arcs and shapes, not listed
Dimensions:
  circle w0.1: c0,0 r13.985
  circle w0.1: c0,0 r22.225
